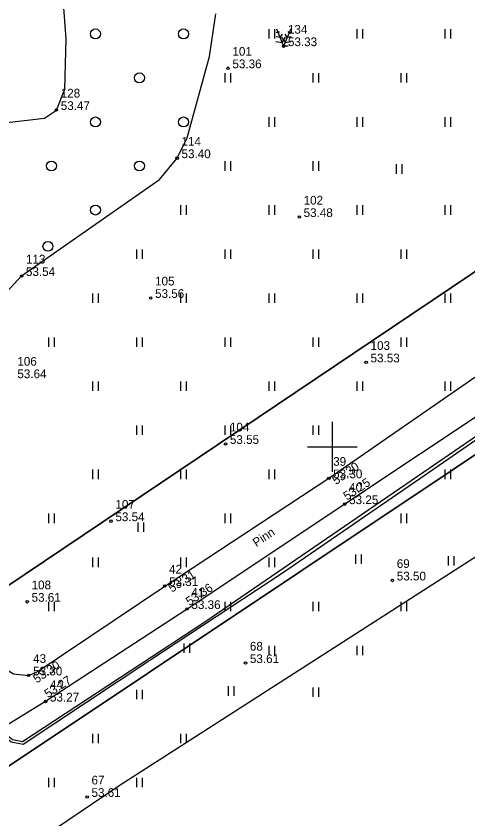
# Model space of a CAD drawing. Extents: x 538599 to 541973, y 6559689 to 6564516.
# Drawn here: x 540574.6 to 540610.9, y 6561220.1 to 6561284.6 of the extents above; entities that cross this region are included whole.
import ezdxf

# ---------------------------------------------------------------- set-up
doc = ezdxf.new("R2010")
doc.units = 0
for name, color, linetype in [('HALJASTUS', 7, 'Continuous'), ('KORGUS-EH2000', 7, 'Continuous'), ('KPKAABEL', 7, 'Continuous'), ('MOOTKORG-EH2000', 7, 'Continuous'), ('MOOTMPUNKT', 7, 'Continuous'), ('MOOTNR', 7, 'Continuous'), ('MOOTPIIR', 7, 'Continuous'), ('MPKAABEL', 7, 'Continuous'), ('PIIR', 7, 'Continuous'), ('PUU', 7, 'Continuous'), ('TEE', 7, 'Continuous'), ('VORK', 7, 'Continuous')]:
    doc.layers.add(name, color=color, linetype=linetype)

msp = doc.modelspace()

# ---------------------------------------------------------------- linework, layer by layer
at = {"layer": 'HALJASTUS'}
for p, q in [((540594.89, 6561283.536), (540594.89, 6561282.775)), ((540595.345, 6561283.536), (540595.345, 6561282.775)), ((540601.961, 6561283.536), (540601.961, 6561282.775)), ((540602.416, 6561283.536), (540602.416, 6561282.775)), ((540609.032, 6561283.536), (540609.032, 6561282.775)), ((540609.487, 6561283.536), (540609.487, 6561282.775)), ((540591.354, 6561280), (540591.354, 6561279.239)), ((540591.809, 6561280), (540591.809, 6561279.239)), ((540598.425, 6561280), (540598.425, 6561279.239)), ((540598.88, 6561280), (540598.88, 6561279.239)), ((540605.496, 6561280), (540605.496, 6561279.239)), ((540605.951, 6561280), (540605.951, 6561279.239)), ((540594.89, 6561276.465), (540594.89, 6561275.704)), ((540595.345, 6561276.465), (540595.345, 6561275.704)), ((540601.961, 6561276.465), (540601.961, 6561275.704)), ((540602.416, 6561276.465), (540602.416, 6561275.704)), ((540609.032, 6561276.465), (540609.032, 6561275.704)), ((540609.487, 6561276.465), (540609.487, 6561275.704)), ((540591.354, 6561272.929), (540591.354, 6561272.168)), ((540591.809, 6561272.929), (540591.809, 6561272.168)), ((540598.425, 6561272.929), (540598.425, 6561272.168)), ((540598.88, 6561272.929), (540598.88, 6561272.168)), ((540605.131, 6561272.687), (540605.131, 6561271.926)), ((540605.586, 6561272.687), (540605.586, 6561271.926)), ((540587.818, 6561269.394), (540587.818, 6561268.633)), ((540588.274, 6561269.394), (540588.274, 6561268.633)), ((540594.89, 6561269.394), (540594.89, 6561268.633)), ((540595.345, 6561269.394), (540595.345, 6561268.633)), ((540601.961, 6561269.394), (540601.961, 6561268.633)), ((540602.416, 6561269.394), (540602.416, 6561268.633)), ((540609.032, 6561269.394), (540609.032, 6561268.633)), ((540609.487, 6561269.394), (540609.487, 6561268.633)), ((540584.283, 6561265.858), (540584.283, 6561265.097)), ((540584.738, 6561265.858), (540584.738, 6561265.097)), ((540591.354, 6561265.858), (540591.354, 6561265.097)), ((540591.809, 6561265.858), (540591.809, 6561265.097)), ((540598.425, 6561265.858), (540598.425, 6561265.097)), ((540598.88, 6561265.858), (540598.88, 6561265.097)), ((540605.496, 6561265.858), (540605.496, 6561265.097)), ((540605.951, 6561265.858), (540605.951, 6561265.097)), ((540580.747, 6561262.323), (540580.747, 6561261.562)), ((540581.202, 6561262.323), (540581.202, 6561261.562)), ((540587.818, 6561262.323), (540587.818, 6561261.562)), ((540588.274, 6561262.323), (540588.274, 6561261.562)), ((540594.89, 6561262.323), (540594.89, 6561261.562)), ((540595.345, 6561262.323), (540595.345, 6561261.562)), ((540601.961, 6561262.323), (540601.961, 6561261.562)), ((540602.416, 6561262.323), (540602.416, 6561261.562)), ((540609.032, 6561262.323), (540609.032, 6561261.562)), ((540609.487, 6561262.323), (540609.487, 6561261.562)), ((540577.212, 6561258.787), (540577.212, 6561258.026)), ((540577.667, 6561258.787), (540577.667, 6561258.026)), ((540584.283, 6561258.787), (540584.283, 6561258.026)), ((540584.738, 6561258.787), (540584.738, 6561258.026)), ((540591.354, 6561258.787), (540591.354, 6561258.026)), ((540591.809, 6561258.787), (540591.809, 6561258.026)), ((540598.425, 6561258.787), (540598.425, 6561258.026)), ((540598.88, 6561258.787), (540598.88, 6561258.026)), ((540605.496, 6561258.787), (540605.496, 6561258.026)), ((540605.951, 6561258.787), (540605.951, 6561258.026)), ((540580.747, 6561255.252), (540580.747, 6561254.491)), ((540581.202, 6561255.252), (540581.202, 6561254.491)), ((540587.818, 6561255.252), (540587.818, 6561254.491)), ((540588.274, 6561255.252), (540588.274, 6561254.491)), ((540594.89, 6561255.252), (540594.89, 6561254.491)), ((540595.345, 6561255.252), (540595.345, 6561254.491)), ((540601.961, 6561255.252), (540601.961, 6561254.491)), ((540602.416, 6561255.252), (540602.416, 6561254.491)), ((540609.032, 6561255.252), (540609.032, 6561254.491)), ((540609.487, 6561255.252), (540609.487, 6561254.491)), ((540584.283, 6561251.716), (540584.283, 6561250.955)), ((540584.738, 6561251.716), (540584.738, 6561250.955)), ((540591.354, 6561251.716), (540591.354, 6561250.955)), ((540591.809, 6561251.716), (540591.809, 6561250.955)), ((540598.425, 6561251.716), (540598.425, 6561250.955)), ((540598.88, 6561251.716), (540598.88, 6561250.955)), ((540580.747, 6561248.181), (540580.747, 6561247.42)), ((540581.202, 6561248.181), (540581.202, 6561247.42)), ((540587.818, 6561248.181), (540587.818, 6561247.42)), ((540588.274, 6561248.181), (540588.274, 6561247.42)), ((540594.89, 6561248.181), (540594.89, 6561247.42)), ((540595.345, 6561248.181), (540595.345, 6561247.42)), ((540609.032, 6561248.181), (540609.032, 6561247.42)), ((540609.487, 6561248.181), (540609.487, 6561247.42)), ((540577.212, 6561244.645), (540577.212, 6561243.884)), ((540577.667, 6561244.645), (540577.667, 6561243.884)), ((540591.354, 6561244.645), (540591.354, 6561243.884)), ((540591.809, 6561244.645), (540591.809, 6561243.884)), ((540605.496, 6561244.645), (540605.496, 6561243.884)), ((540605.951, 6561244.645), (540605.951, 6561243.884)), ((540584.374, 6561243.939), (540584.374, 6561243.178)), ((540584.829, 6561243.939), (540584.829, 6561243.178)), ((540580.747, 6561241.11), (540580.747, 6561240.348)), ((540581.202, 6561241.11), (540581.202, 6561240.348)), ((540587.818, 6561241.11), (540587.818, 6561240.348)), ((540588.274, 6561241.11), (540588.274, 6561240.348)), ((540594.89, 6561241.11), (540594.89, 6561240.348)), ((540595.345, 6561241.11), (540595.345, 6561240.348)), ((540601.85, 6561241.374), (540601.85, 6561240.613)), ((540602.305, 6561241.374), (540602.305, 6561240.613)), ((540609.304, 6561241.229), (540609.304, 6561240.468)), ((540609.759, 6561241.229), (540609.759, 6561240.468)), ((540577.212, 6561237.574), (540577.212, 6561236.813)), ((540577.667, 6561237.574), (540577.667, 6561236.813)), ((540591.354, 6561237.574), (540591.354, 6561236.813)), ((540591.809, 6561237.574), (540591.809, 6561236.813)), ((540598.425, 6561237.574), (540598.425, 6561236.813)), ((540598.88, 6561237.574), (540598.88, 6561236.813)), ((540605.496, 6561237.574), (540605.496, 6561236.813)), ((540605.951, 6561237.574), (540605.951, 6561236.813)), ((540588.061, 6561234.229), (540588.061, 6561233.467)), ((540588.516, 6561234.229), (540588.516, 6561233.467)), ((540594.89, 6561234.039), (540594.89, 6561233.277)), ((540595.345, 6561234.039), (540595.345, 6561233.277)), ((540601.961, 6561234.039), (540601.961, 6561233.277)), ((540602.416, 6561234.039), (540602.416, 6561233.277)), ((540591.643, 6561230.79), (540591.643, 6561230.029)), ((540592.098, 6561230.79), (540592.098, 6561230.029)), ((540598.425, 6561230.687), (540598.425, 6561229.926)), ((540598.88, 6561230.687), (540598.88, 6561229.926)), ((540584.283, 6561230.503), (540584.283, 6561229.742)), ((540584.738, 6561230.503), (540584.738, 6561229.742)), ((540580.747, 6561226.967), (540580.747, 6561226.206)), ((540581.202, 6561226.967), (540581.202, 6561226.206)), ((540587.818, 6561226.967), (540587.818, 6561226.206)), ((540588.274, 6561226.967), (540588.274, 6561226.206)), ((540577.212, 6561223.432), (540577.212, 6561222.671)), ((540577.667, 6561223.432), (540577.667, 6561222.671)), ((540584.283, 6561223.432), (540584.283, 6561222.671)), ((540584.738, 6561223.432), (540584.738, 6561222.671))]:
    msp.add_line(p, q, dxfattribs=at)
for points in [[(540570.802, 6561276.809), (540573.412, 6561275.976), (540576.87, 6561276.39), (540577.836, 6561277.043), (540578.505, 6561278.71), (540578.609, 6561282.748), (540578.298, 6561287.056), (540577.866, 6561289.9), (540576.248, 6561292.214), (540572.273, 6561295.155), (540567.268, 6561297.994), (540566.387, 6561298.177), (540565.922, 6561297.598), (540564.985, 6561294.225), (540565.068, 6561290.756), (540565.634, 6561288.817), (540567.508, 6561285.194), (540569.933, 6561277.546), (540570.802, 6561276.809)], [(540561.062, 6561256.876), (540561.766, 6561255.487), (540562.959, 6561254.486), (540563.979, 6561254.35), (540566.676, 6561254.836), (540568.605, 6561255.581), (540569.809, 6561256.895), (540572.418, 6561260.901), (540575.042, 6561263.719), (540586.108, 6561271.474), (540587.537, 6561273.178), (540588.329, 6561274.808), (540590.147, 6561281.335), (540590.644, 6561284.753)]]:
    msp.add_lwpolyline(points, dxfattribs=at)
for centre in [(540580.975, 6561283.155), (540588.046, 6561283.155), (540584.51, 6561279.62), (540580.975, 6561276.084), (540588.046, 6561276.084), (540577.439, 6561272.549), (540584.51, 6561272.549), (540580.975, 6561269.013), (540577.158, 6561266.1)]:
    msp.add_circle(centre, 0.4, dxfattribs=at)
at = {"layer": 'KORGUS-EH2000'}
for centre in [(540591.627, 6561280.396), (540577.836, 6561277.043), (540587.537, 6561273.178), (540597.345, 6561268.451), (540575.042, 6561263.719), (540585.412, 6561261.958), (540602.722, 6561256.784), (540591.425, 6561250.237), (540599.72, 6561247.482), (540601.001, 6561245.406), (540582.23, 6561244.038), (540604.826, 6561239.279), (540586.536, 6561238.83), (540575.495, 6561237.567), (540588.333, 6561236.983), (540593.03, 6561232.647), (540575.618, 6561231.655), (540576.973, 6561229.557), (540580.308, 6561221.901)]:
    msp.add_circle(centre, 0.1, dxfattribs=at)
at = {"layer": 'KPKAABEL'}
msp.add_lwpolyline([(540612.707, 6561251.641), (540589.754, 6561235.922), (540575.113, 6561226.32), (540574.309, 6561226.488), (540572.813, 6561227.652), (540566.988, 6561234.121), (540563.285, 6561239.03), (540553.802, 6561251.292), (540538.41, 6561271.219), (540529.488, 6561282.512), (540526.272, 6561286.879), (540510.559, 6561306.203), (540484.617, 6561338.574), (540463.547, 6561364.405), (540438.892, 6561393.697), (540425.441, 6561409.211), (540424.922, 6561409.461), (540423.725, 6561408.808), (540421.719, 6561406.34), (540419.82, 6561404.72)], dxfattribs=at)
at = {"layer": 'MOOTMPUNKT'}
for centre in [(540596.087, 6561282.169), (540591.627, 6561280.396), (540577.836, 6561277.043), (540587.537, 6561273.178), (540597.345, 6561268.451), (540575.042, 6561263.719), (540585.412, 6561261.958), (540602.722, 6561256.784), (540591.425, 6561250.237), (540599.72, 6561247.482), (540601.001, 6561245.406), (540582.23, 6561244.038), (540604.826, 6561239.279), (540586.536, 6561238.83), (540575.495, 6561237.567), (540588.333, 6561236.983), (540593.03, 6561232.647), (540575.618, 6561231.655), (540576.973, 6561229.557), (540580.308, 6561221.901)]:
    msp.add_circle(centre, 0.1, dxfattribs=at)
at = {"layer": 'MOOTPIIR'}
msp.add_lwpolyline([(540384.887, 6561443.845), (540403.973, 6561422.469), (540424.304, 6561399.698), (540444.636, 6561376.927), (540453.177, 6561363.987), (540470.995, 6561343.689), (540492.689, 6561318.976), (540511.766, 6561294.341), (540521.974, 6561279.181), (540525.589, 6561267.954), (540536.495, 6561252.794), (540542.772, 6561231.926), (540526.603, 6561219.05), (540510.624, 6561213.468), (540498.26, 6561199.196), (540484.564, 6561192.98), (540479.618, 6561185.622), (540478.413, 6561178.328), (540490.461, 6561165.832), (540493.58, 6561162.597), (540531.105, 6561187.906), (540582.869, 6561222.817), (540621.742, 6561247.747)], dxfattribs=at)
at = {"layer": 'MPKAABEL'}
msp.add_lwpolyline([(540624.746, 6561259.652), (540607.46, 6561247.735), (540595.988, 6561239.875), (540585.355, 6561232.862), (540575.156, 6561226.105), (540574.211, 6561226.297), (540572.668, 6561227.5), (540566.836, 6561233.992), (540559.418, 6561243.82), (540553.652, 6561251.158), (540543.068, 6561264.797), (540529.488, 6561282.18), (540528.898, 6561282.254), (540529.176, 6561282.594), (540526.037, 6561286.855), (540522.472, 6561291.297), (540514.38, 6561301.154), (540496.217, 6561323.662), (540475.169, 6561349.87)], dxfattribs=at)
at = {"layer": 'PIIR'}
for points in [[(540491.21, 6561183.5), (540566.07, 6561233.36), (540528.84, 6561281.85), (540494.34, 6561324.62), (540458.27, 6561368.69), (540424.68, 6561408.57), (540384.55, 6561455.73), (540346.17, 6561499.11), (540330.12, 6561517.14), (540337.36, 6561523.32), (540348.28, 6561532.96), (540364.11, 6561514.94), (540353.14, 6561505.27), (540391.51, 6561461.86), (540431.74, 6561414.74), (540465.17, 6561374.89), (540501.31, 6561330.86), (540535.92, 6561287.97), (540573.77, 6561238.75), (540640.63, 6561283.66), (540646.74, 6561272.89), (540499, 6561174.36)], [(540535.92, 6561287.97), (540606.26, 6561333.96), (540640.63, 6561283.66), (540573.77, 6561238.75)], [(540490.55, 6561169.03), (540499, 6561174.36), (540646.74, 6561272.89), (540687.02, 6561204.55), (540544.29, 6561102.63)]]:
    msp.add_lwpolyline(points, close=True, dxfattribs=at)
at = {"layer": 'PUU'}
for p, q in [((540595.505, 6561283.551), (540596.087, 6561282.169)), ((540596.669, 6561283.551), (540596.087, 6561282.169)), ((540595.796, 6561282.86), (540595.481, 6561282.92)), ((540595.641, 6561283.229), (540595.494, 6561283.257)), ((540595.723, 6561283.354), (540595.641, 6561283.229)), ((540595.973, 6561283.127), (540595.796, 6561282.86)), ((540595.925, 6561282.877), (540596.206, 6561282.451)), ((540595.968, 6561282.451), (540596.249, 6561282.877)), ((540596.378, 6561282.86), (540596.201, 6561283.127)), ((540596.693, 6561282.92), (540596.378, 6561282.86)), ((540596.533, 6561283.229), (540596.451, 6561283.354)), ((540596.68, 6561283.257), (540596.533, 6561283.229)), ((540595.467, 6561282.547), (540595.968, 6561282.451)), ((540596.206, 6561282.451), (540596.707, 6561282.547)), ((540596.447, 6561282.169), (540596.087, 6561282.169))]:
    msp.add_line(p, q, dxfattribs=at)
at = {"layer": 'TEE'}
for points in [[(540480.237, 6561350.173), (540490.343, 6561338.333), (540499.283, 6561327.538), (540509.455, 6561315.157), (540515.302, 6561308.183), (540518.538, 6561303.936), (540527.782, 6561291.781), (540530.574, 6561288.237), (540536.213, 6561281.563), (540545.977, 6561268.786), (540548.214, 6561265.824), (540555.649, 6561256.763), (540560.731, 6561250.307), (540563.896, 6561245.79), (540566.417, 6561241.84), (540570.085, 6561235.281), (540571.311, 6561233.896), (540572.286, 6561233.082), (540574.391, 6561231.792), (540575.618, 6561231.655), (540576.368, 6561231.987), (540586.536, 6561238.83), (540599.72, 6561247.482), (540611.437, 6561255.604)], [(540651.018, 6561277.76), (540649.299, 6561277.32), (540647.947, 6561276.705), (540637.204, 6561268.881), (540625.631, 6561261.527), (540617.283, 6561256.229), (540613.091, 6561253.422), (540601.001, 6561245.406), (540588.333, 6561236.983), (540576.973, 6561229.557), (540565.171, 6561222.344), (540552.563, 6561213.52), (540540.165, 6561205.325), (540527.674, 6561197.002), (540515.613, 6561188.752), (540503.253, 6561180.454), (540486.571, 6561169.867)]]:
    msp.add_lwpolyline(points, dxfattribs=at)
at = {"layer": 'VORK'}
for p, q in [((540600, 6561252), (540600, 6561248)), ((540598, 6561250), (540602, 6561250))]:
    msp.add_line(p, q, dxfattribs=at)

# ---------------------------------------------------------------- texts
at = {"layer": 'KORGUS-EH2000'}
for s, p in [('53.36', (540591.977, 6561280.396)), ('53.47', (540578.186, 6561277.043)), ('53.40', (540587.887, 6561273.178)), ('53.48', (540597.695, 6561268.451)), ('53.54', (540575.392, 6561263.719)), ('53.56', (540585.762, 6561261.958)), ('53.53', (540603.072, 6561256.784)), ('53.64', (540574.703, 6561255.517)), ('53.55', (540591.775, 6561250.237)), ('53.54', (540582.58, 6561244.038)), ('53.50', (540605.176, 6561239.279)), ('53.61', (540575.845, 6561237.567)), ('53.61', (540593.38, 6561232.647)), ('53.61', (540580.658, 6561221.901))]:
    msp.add_text(s, height=0.7, dxfattribs=at).set_placement(p)
for s, rotation, p in [('53.30', 34.72896, (540600.303, 6561246.929)), ('53.25', 33.54546, (540601.175, 6561245.677)), ('53.31', 33.27489, (540587.12, 6561238.292)), ('53.36', 33.62008, (540588.528, 6561237.22)), ('53.30', 33.93819, (540576.265, 6561230.999)), ('53.27', 33.17253, (540577.156, 6561229.814))]:
    msp.add_text(s, height=0.7, rotation=rotation, dxfattribs=at).set_placement(p)
at = {"layer": 'MOOTKORG-EH2000'}
for s, p in [('53.33', (540596.437, 6561282.169)), ('53.36', (540591.977, 6561280.396)), ('53.47', (540578.186, 6561277.043)), ('53.40', (540587.887, 6561273.178)), ('53.48', (540597.695, 6561268.451)), ('53.54', (540575.392, 6561263.719)), ('53.56', (540585.762, 6561261.958)), ('53.53', (540603.072, 6561256.784)), ('53.64', (540574.703, 6561255.517)), ('53.55', (540591.775, 6561250.237)), ('53.30', (540600.07, 6561247.482)), ('53.25', (540601.351, 6561245.406)), ('53.54', (540582.58, 6561244.038)), ('53.50', (540605.176, 6561239.279)), ('53.31', (540586.886, 6561238.83)), ('53.61', (540575.845, 6561237.567)), ('53.36', (540588.683, 6561236.983)), ('53.61', (540593.38, 6561232.647)), ('53.30', (540575.968, 6561231.655)), ('53.27', (540577.323, 6561229.557)), ('53.61', (540580.658, 6561221.901))]:
    msp.add_text(s, height=0.7, dxfattribs=at).set_placement(p)
at = {"layer": 'MOOTNR'}
for s, p in [('134', (540596.437, 6561283.169)), ('101', (540591.977, 6561281.396)), ('128', (540578.186, 6561278.043)), ('114', (540587.887, 6561274.178)), ('102', (540597.695, 6561269.451)), ('113', (540575.392, 6561264.719)), ('105', (540585.762, 6561262.958)), ('103', (540603.072, 6561257.784)), ('106', (540574.703, 6561256.517)), ('104', (540591.775, 6561251.237)), ('39', (540600.07, 6561248.482)), ('40', (540601.351, 6561246.406)), ('107', (540582.58, 6561245.038)), ('69', (540605.176, 6561240.279)), ('42', (540586.886, 6561239.83)), ('108', (540575.845, 6561238.567)), ('41', (540588.683, 6561237.983)), ('68', (540593.38, 6561233.647)), ('43', (540575.968, 6561232.655)), ('44', (540577.323, 6561230.557)), ('67', (540580.658, 6561222.901))]:
    msp.add_text(s, height=0.7, dxfattribs=at).set_placement(p)
at = {"layer": 'TEE'}
msp.add_text('Pinn', height=0.7, rotation=33.62008, dxfattribs=at).set_placement((540593.9, 6561241.945))

doc.saveas('drawing.dxf')
